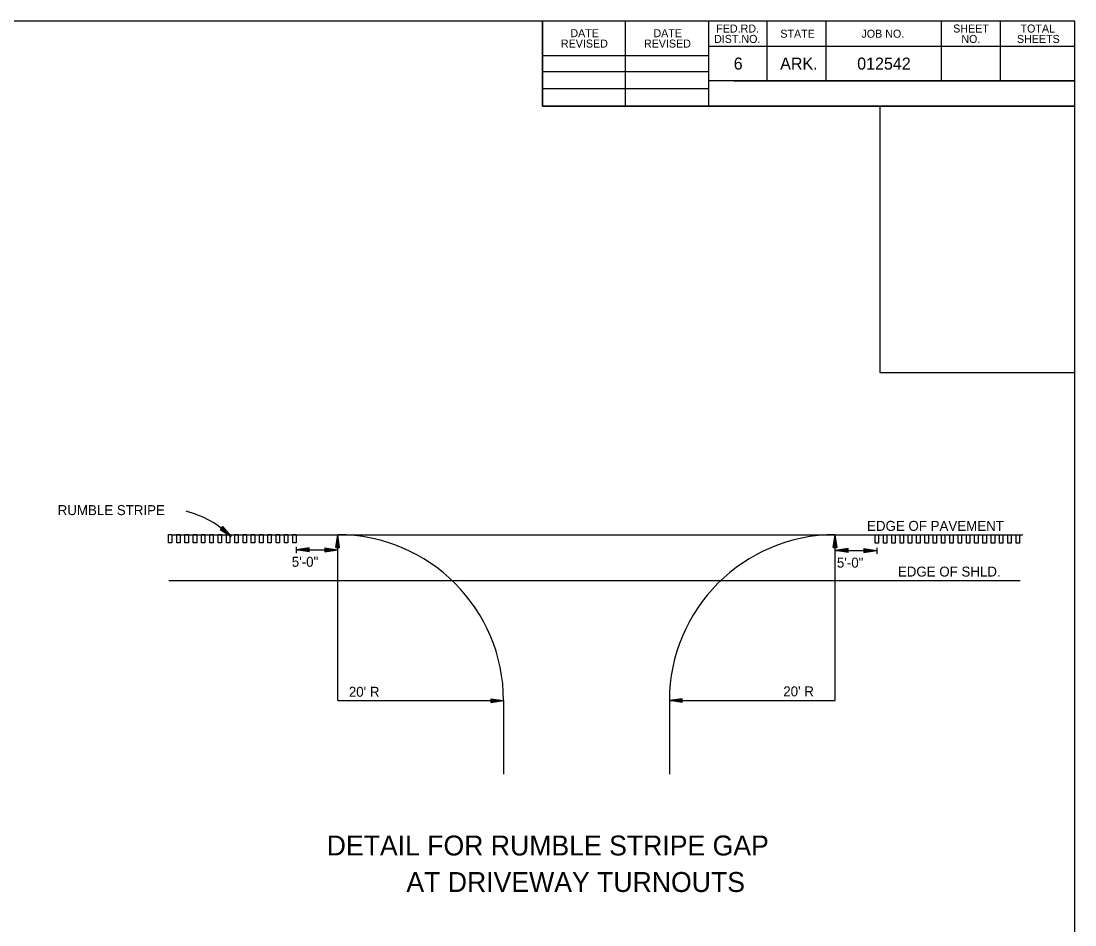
# Model space of a CAD drawing. Extents: x 1371343 to 1376243, y 378740 to 382184.
# Drawn here: x 1372386 to 1373018, y 380374 to 380915 of the extents above; entities that cross this region are included whole.
import ezdxf

# ---------------------------------------------------------------- set-up
doc = ezdxf.new("R2010")
doc.units = 0
for name, color, linetype in [('Default', 7, 'Continuous'), ('SHET_Annotations', 7, 'Continuous'), ('SHET_Border-Lines', 7, 'Continuous'), ('SHET_Border-Text', 7, 'Continuous'), ('SHET_Stamp-Prelim', 7, 'Continuous'), ('SHET_Stamp-Seal', 7, 'Continuous')]:
    doc.layers.add(name, color=color, linetype=linetype)

msp = doc.modelspace()

# ---------------------------------------------------------------- linework, layer by layer
at = {"layer": 'Default'}
for p, q in [((1372506.53, 380612.35), (1372505.05, 380610.58)), ((1372505.55, 380611.18), (1372507.71, 380609.85)), ((1372505.67, 380611.33), (1372506.72, 380610.68)), ((1372505.91, 380611.6), (1372506.72, 380610.68)), ((1372506.03, 380611.75), (1372507.71, 380609.85)), ((1372506.16, 380611.91), (1372508.71, 380609.01)), ((1372506.28, 380612.05), (1372509.69, 380608.19)), ((1372506.41, 380612.2), (1372510.71, 380607.34)), ((1372506.53, 380612.35), (1372511.69, 380606.51)), ((1372475.93, 380607.52), (1372986.72, 380607.52)), ((1372505.05, 380610.58), (1372511.69, 380606.51)), ((1372505.17, 380610.73), (1372510.71, 380607.34)), ((1372505.3, 380610.88), (1372509.69, 380608.19)), ((1372505.42, 380611.03), (1372508.71, 380609.01)), ((1372574.44, 380599.82), (1372575.6, 380607.52)), ((1372574.44, 380599.82), (1372575.6, 380607.52)), ((1372574.64, 380599.82), (1372575.6, 380606.24)), ((1372574.64, 380599.82), (1372575.6, 380606.24)), ((1372574.83, 380599.82), (1372575.6, 380604.91)), ((1372574.83, 380599.82), (1372575.6, 380604.91)), ((1372575.6, 380508.02), (1372575.6, 380607.52)), ((1372576.76, 380599.82), (1372575.6, 380607.52)), ((1372576.76, 380599.82), (1372575.6, 380607.52)), ((1372576.56, 380599.82), (1372575.6, 380606.24)), ((1372576.56, 380599.82), (1372575.6, 380606.24)), ((1372576.37, 380599.82), (1372575.6, 380604.91)), ((1372576.37, 380599.82), (1372575.6, 380604.91)), ((1372872.97, 380599.82), (1372874.12, 380607.52)), ((1372872.97, 380599.82), (1372874.12, 380607.52)), ((1372873.16, 380599.82), (1372874.12, 380606.24)), ((1372873.16, 380599.82), (1372874.12, 380606.24)), ((1372873.35, 380599.82), (1372874.12, 380604.91)), ((1372873.35, 380599.82), (1372874.12, 380604.91)), ((1372874.12, 380508.02), (1372874.12, 380607.52)), ((1372875.28, 380599.82), (1372874.12, 380607.52)), ((1372875.28, 380599.82), (1372874.12, 380607.52)), ((1372875.08, 380599.82), (1372874.12, 380606.24)), ((1372875.08, 380599.82), (1372874.12, 380606.24)), ((1372874.89, 380599.82), (1372874.12, 380604.91)), ((1372874.89, 380599.82), (1372874.12, 380604.91)), ((1372550.73, 380600.19), (1372550.73, 380596.51)), ((1372558.43, 380599.64), (1372550.73, 380598.48)), ((1372550.73, 380598.48), (1372575.6, 380598.48)), ((1372558.43, 380597.33), (1372550.73, 380598.48)), ((1372558.43, 380599.45), (1372552.01, 380598.48)), ((1372558.43, 380597.52), (1372552.01, 380598.48)), ((1372558.43, 380599.25), (1372553.34, 380598.48)), ((1372558.43, 380597.72), (1372553.34, 380598.48)), ((1372558.43, 380599.06), (1372554.62, 380598.48)), ((1372558.43, 380597.91), (1372554.62, 380598.48)), ((1372558.43, 380598.86), (1372555.93, 380598.48)), ((1372558.43, 380598.11), (1372555.93, 380598.48)), ((1372558.43, 380598.66), (1372557.21, 380598.48)), ((1372558.43, 380598.3), (1372557.21, 380598.48)), ((1372558.43, 380597.33), (1372558.43, 380599.64)), ((1372567.89, 380599.64), (1372575.6, 380598.48)), ((1372567.89, 380599.64), (1372567.89, 380597.33)), ((1372567.89, 380599.45), (1372574.31, 380598.48)), ((1372567.89, 380599.25), (1372572.99, 380598.48)), ((1372567.89, 380599.06), (1372571.7, 380598.48)), ((1372567.89, 380598.86), (1372570.4, 380598.48)), ((1372567.89, 380598.66), (1372569.11, 380598.48)), ((1372567.89, 380597.33), (1372575.6, 380598.48)), ((1372567.89, 380598.11), (1372570.4, 380598.48)), ((1372567.89, 380597.72), (1372572.99, 380598.48)), ((1372567.89, 380597.52), (1372574.31, 380598.48)), ((1372567.89, 380597.91), (1372571.7, 380598.48)), ((1372567.89, 380598.3), (1372569.11, 380598.48)), ((1372574.44, 380599.82), (1372576.76, 380599.82)), ((1372574.44, 380599.82), (1372576.76, 380599.82)), ((1372575.03, 380599.82), (1372575.6, 380603.63)), ((1372575.03, 380599.82), (1372575.6, 380603.63)), ((1372575.23, 380599.82), (1372575.6, 380602.32)), ((1372575.23, 380599.82), (1372575.6, 380602.32)), ((1372575.42, 380599.82), (1372575.6, 380601.04)), ((1372575.42, 380599.82), (1372575.6, 380601.04)), ((1372576.17, 380599.82), (1372575.6, 380603.63)), ((1372576.17, 380599.82), (1372575.6, 380603.63)), ((1372575.98, 380599.82), (1372575.6, 380602.32)), ((1372575.98, 380599.82), (1372575.6, 380602.32)), ((1372575.78, 380599.82), (1372575.6, 380601.04)), ((1372575.78, 380599.82), (1372575.6, 380601.04)), ((1372872.97, 380599.82), (1372875.28, 380599.82)), ((1372872.97, 380599.82), (1372875.28, 380599.82)), ((1372873.55, 380599.82), (1372874.12, 380603.63)), ((1372873.55, 380599.82), (1372874.12, 380603.63)), ((1372873.75, 380599.82), (1372874.12, 380602.32)), ((1372873.75, 380599.82), (1372874.12, 380602.32)), ((1372873.94, 380599.82), (1372874.12, 380601.04)), ((1372873.94, 380599.82), (1372874.12, 380601.04)), ((1372874.69, 380599.82), (1372874.12, 380603.63)), ((1372874.69, 380599.82), (1372874.12, 380603.63)), ((1372874.5, 380599.82), (1372874.12, 380602.32)), ((1372874.5, 380599.82), (1372874.12, 380602.32)), ((1372874.3, 380599.82), (1372874.12, 380601.04)), ((1372874.3, 380599.82), (1372874.12, 380601.04)), ((1372881.83, 380599.19), (1372874.12, 380598.03)), ((1372881.83, 380598.99), (1372875.41, 380598.03)), ((1372881.83, 380598.8), (1372876.73, 380598.03)), ((1372881.83, 380598.6), (1372878.02, 380598.03)), ((1372881.83, 380598.41), (1372879.32, 380598.03)), ((1372881.83, 380596.87), (1372881.83, 380599.19)), ((1372891.29, 380599.19), (1372898.99, 380598.03)), ((1372891.29, 380599.19), (1372891.29, 380596.87)), ((1372891.29, 380598.99), (1372897.71, 380598.03)), ((1372891.29, 380598.8), (1372896.38, 380598.03)), ((1372891.29, 380598.6), (1372895.1, 380598.03)), ((1372891.29, 380598.4), (1372893.79, 380598.03)), ((1372898.99, 380599.74), (1372898.99, 380596.06)), ((1372874.12, 380598.03), (1372898.99, 380598.03)), ((1372881.83, 380596.87), (1372874.12, 380598.03)), ((1372881.83, 380597.07), (1372875.41, 380598.03)), ((1372881.83, 380597.26), (1372876.73, 380598.03)), ((1372881.83, 380597.46), (1372878.02, 380598.03)), ((1372881.83, 380597.66), (1372879.32, 380598.03)), ((1372881.83, 380598.21), (1372880.61, 380598.03)), ((1372881.83, 380597.85), (1372880.61, 380598.03)), ((1372891.29, 380598.21), (1372892.51, 380598.03)), ((1372891.29, 380596.87), (1372898.99, 380598.03)), ((1372891.29, 380597.65), (1372893.79, 380598.03)), ((1372891.29, 380597.26), (1372896.38, 380598.03)), ((1372891.29, 380597.07), (1372897.71, 380598.03)), ((1372891.29, 380597.46), (1372895.1, 380598.03)), ((1372891.29, 380597.85), (1372892.51, 380598.03)), ((1372474.28, 380580.11), (1372985.07, 380580.11)), ((1372575.6, 380508.02), (1372675.11, 380508.02)), ((1372667.4, 380509.17), (1372675.11, 380508.02)), ((1372667.4, 380509.17), (1372667.4, 380506.86)), ((1372667.4, 380509.17), (1372675.11, 380508.02)), ((1372667.4, 380509.17), (1372667.4, 380506.86)), ((1372667.4, 380508.98), (1372673.82, 380508.02)), ((1372667.4, 380508.98), (1372673.82, 380508.02)), ((1372667.4, 380508.78), (1372672.49, 380508.02)), ((1372667.4, 380508.78), (1372672.49, 380508.02)), ((1372667.4, 380508.59), (1372671.21, 380508.02)), ((1372667.4, 380508.59), (1372671.21, 380508.02)), ((1372667.4, 380508.39), (1372669.91, 380508.02)), ((1372667.4, 380508.39), (1372669.91, 380508.02)), ((1372667.4, 380508.2), (1372668.62, 380508.02)), ((1372667.4, 380508.2), (1372668.62, 380508.02)), ((1372667.4, 380506.86), (1372675.11, 380508.02)), ((1372667.4, 380507.64), (1372669.91, 380508.02)), ((1372667.4, 380507.25), (1372672.49, 380508.02)), ((1372667.4, 380507.05), (1372673.82, 380508.02)), ((1372667.4, 380507.44), (1372671.21, 380508.02)), ((1372667.4, 380507.84), (1372668.62, 380508.02)), ((1372667.4, 380506.86), (1372675.11, 380508.02)), ((1372667.4, 380507.64), (1372669.91, 380508.02)), ((1372667.4, 380507.25), (1372672.49, 380508.02)), ((1372667.4, 380507.05), (1372673.82, 380508.02)), ((1372667.4, 380507.44), (1372671.21, 380508.02)), ((1372667.4, 380507.84), (1372668.62, 380508.02)), ((1372675.11, 380508.02), (1372675.11, 380463.96)), ((1372782.32, 380509.17), (1372774.61, 380508.02)), ((1372782.32, 380509.17), (1372774.61, 380508.02)), ((1372774.61, 380508.02), (1372774.61, 380463.96)), ((1372774.61, 380508.02), (1372874.12, 380508.02)), ((1372782.32, 380506.86), (1372774.61, 380508.02)), ((1372782.32, 380506.86), (1372774.61, 380508.02)), ((1372782.32, 380508.98), (1372775.9, 380508.02)), ((1372782.32, 380508.98), (1372775.9, 380508.02)), ((1372782.32, 380507.05), (1372775.9, 380508.02)), ((1372782.32, 380507.05), (1372775.9, 380508.02)), ((1372782.32, 380508.78), (1372777.23, 380508.02)), ((1372782.32, 380508.78), (1372777.23, 380508.02)), ((1372782.32, 380507.25), (1372777.23, 380508.02)), ((1372782.32, 380507.25), (1372777.23, 380508.02)), ((1372782.32, 380508.59), (1372778.51, 380508.02)), ((1372782.32, 380508.59), (1372778.51, 380508.02)), ((1372782.32, 380507.44), (1372778.51, 380508.02)), ((1372782.32, 380507.44), (1372778.51, 380508.02)), ((1372782.32, 380508.39), (1372779.81, 380508.02)), ((1372782.32, 380508.39), (1372779.81, 380508.02)), ((1372782.32, 380507.64), (1372779.81, 380508.02)), ((1372782.32, 380507.64), (1372779.81, 380508.02)), ((1372782.32, 380508.2), (1372781.1, 380508.02)), ((1372782.32, 380508.2), (1372781.1, 380508.02)), ((1372782.32, 380507.84), (1372781.1, 380508.02)), ((1372782.32, 380507.84), (1372781.1, 380508.02)), ((1372782.32, 380506.86), (1372782.32, 380509.17)), ((1372782.32, 380506.86), (1372782.32, 380509.17))]:
    msp.add_line(p, q, dxfattribs=at)
for points in [[(1372474.03, 380602.59), (1372474.03, 380607.57), (1372476.11, 380607.57), (1372476.11, 380602.59), (1372474.03, 380602.59)], [(1372479.01, 380602.59), (1372479.01, 380607.57), (1372481.08, 380607.57), (1372481.08, 380602.59), (1372479.01, 380602.59)], [(1372483.98, 380602.59), (1372483.98, 380607.57), (1372486.06, 380607.57), (1372486.06, 380602.59), (1372483.98, 380602.59)], [(1372488.96, 380602.59), (1372488.96, 380607.57), (1372491.03, 380607.57), (1372491.03, 380602.59), (1372488.96, 380602.59)], [(1372493.93, 380602.59), (1372493.93, 380607.57), (1372496, 380607.57), (1372496, 380602.59), (1372493.93, 380602.59)], [(1372498.91, 380602.59), (1372498.91, 380607.57), (1372500.98, 380607.57), (1372500.98, 380602.59), (1372498.91, 380602.59)], [(1372503.88, 380602.59), (1372503.88, 380607.57), (1372505.95, 380607.57), (1372505.95, 380602.59), (1372503.88, 380602.59)], [(1372508.86, 380602.59), (1372508.86, 380607.57), (1372510.93, 380607.57), (1372510.93, 380602.59), (1372508.86, 380602.59)], [(1372513.83, 380602.59), (1372513.83, 380607.57), (1372515.9, 380607.57), (1372515.9, 380602.59), (1372513.83, 380602.59)], [(1372518.81, 380602.59), (1372518.81, 380607.57), (1372520.88, 380607.57), (1372520.88, 380602.59), (1372518.81, 380602.59)], [(1372523.78, 380602.59), (1372523.78, 380607.57), (1372525.85, 380607.57), (1372525.85, 380602.59), (1372523.78, 380602.59)], [(1372528.75, 380602.59), (1372528.75, 380607.57), (1372530.83, 380607.57), (1372530.83, 380602.59), (1372528.75, 380602.59)], [(1372533.73, 380602.59), (1372533.73, 380607.57), (1372535.8, 380607.57), (1372535.8, 380602.59), (1372533.73, 380602.59)], [(1372538.7, 380602.59), (1372538.7, 380607.57), (1372540.78, 380607.57), (1372540.78, 380602.59), (1372538.7, 380602.59)], [(1372543.68, 380602.59), (1372543.68, 380607.57), (1372545.75, 380607.57), (1372545.75, 380602.59), (1372543.68, 380602.59)], [(1372548.65, 380602.59), (1372548.65, 380607.57), (1372550.73, 380607.57), (1372550.73, 380602.59), (1372548.65, 380602.59)], [(1372898.06, 380602.54), (1372898.06, 380607.51), (1372900.13, 380607.51), (1372900.13, 380602.54), (1372898.06, 380602.54)], [(1372903.03, 380602.54), (1372903.03, 380607.51), (1372905.1, 380607.51), (1372905.1, 380602.54), (1372903.03, 380602.54)], [(1372908.01, 380602.54), (1372908.01, 380607.51), (1372910.08, 380607.51), (1372910.08, 380602.54), (1372908.01, 380602.54)], [(1372912.98, 380602.54), (1372912.98, 380607.51), (1372915.05, 380607.51), (1372915.05, 380602.54), (1372912.98, 380602.54)], [(1372917.95, 380602.54), (1372917.95, 380607.51), (1372920.03, 380607.51), (1372920.03, 380602.54), (1372917.95, 380602.54)], [(1372922.93, 380602.54), (1372922.93, 380607.51), (1372925, 380607.51), (1372925, 380602.54), (1372922.93, 380602.54)], [(1372927.9, 380602.54), (1372927.9, 380607.51), (1372929.98, 380607.51), (1372929.98, 380602.54), (1372927.9, 380602.54)], [(1372932.88, 380602.54), (1372932.88, 380607.51), (1372934.95, 380607.51), (1372934.95, 380602.54), (1372932.88, 380602.54)], [(1372937.85, 380602.54), (1372937.85, 380607.51), (1372939.93, 380607.51), (1372939.93, 380602.54), (1372937.85, 380602.54)], [(1372942.83, 380602.54), (1372942.83, 380607.51), (1372944.9, 380607.51), (1372944.9, 380602.54), (1372942.83, 380602.54)], [(1372947.8, 380602.54), (1372947.8, 380607.51), (1372949.88, 380607.51), (1372949.88, 380602.54), (1372947.8, 380602.54)], [(1372952.78, 380602.54), (1372952.78, 380607.51), (1372954.85, 380607.51), (1372954.85, 380602.54), (1372952.78, 380602.54)], [(1372957.75, 380602.54), (1372957.75, 380607.51), (1372959.82, 380607.51), (1372959.82, 380602.54), (1372957.75, 380602.54)], [(1372962.73, 380602.54), (1372962.73, 380607.51), (1372964.8, 380607.51), (1372964.8, 380602.54), (1372962.73, 380602.54)], [(1372967.7, 380602.54), (1372967.7, 380607.51), (1372969.77, 380607.51), (1372969.77, 380602.54), (1372967.7, 380602.54)], [(1372972.68, 380602.54), (1372972.68, 380607.51), (1372974.75, 380607.51), (1372974.75, 380602.54), (1372972.68, 380602.54)], [(1372977.65, 380602.54), (1372977.65, 380607.51), (1372979.72, 380607.51), (1372979.72, 380602.54), (1372977.65, 380602.54)], [(1372982.63, 380602.54), (1372982.63, 380607.51), (1372984.7, 380607.51), (1372984.7, 380602.54), (1372982.63, 380602.54)]]:
    msp.add_lwpolyline(points, dxfattribs=at)
for centre, radius, start, end in [((1372468.86, 380561.43), 62.18, 46.46131, 75.27856), ((1372575.6, 380508.02), 99.51, 0, 90), ((1372874.12, 380508.02), 99.51, 90, 180)]:
    msp.add_arc(centre, radius, start, end, dxfattribs=at)
at = {"layer": 'SHET_Border-Lines'}
for p, q in [((1372698.46, 380864.55), (1372698.46, 380915.49)), ((1372748.28, 380864.55), (1372748.28, 380915.49)), ((1372798.11, 380915.49), (1372798.11, 380864.55)), ((1372832.99, 380915.49), (1372832.99, 380879.71)), ((1372868.39, 380915.49), (1372868.39, 380879.71)), ((1372937.64, 380915.49), (1372937.64, 380879.71)), ((1372973.04, 380915.49), (1372973.04, 380879.71)), ((1373017.92, 380900.34), (1372798.11, 380900.34)), ((1373017.92, 380900.44), (1373017.92, 380900.44)), ((1372698.46, 380894.77), (1372798.11, 380894.77)), ((1372698.46, 380885.18), (1372798.11, 380885.18)), ((1373017.92, 380879.71), (1372798.11, 380879.71)), ((1372813.21, 380879.71), (1373017.92, 380879.71)), ((1372698.46, 380875.17), (1372798.11, 380875.17)), ((1373017.92, 380864.55), (1372698.46, 380864.55))]:
    msp.add_line(p, q, dxfattribs=at)
for points in [[(1371367.92, 379865.49), (1373017.92, 379865.49), (1373017.92, 380915.49), (1371367.92, 380915.49)], [(1372698.46, 380864.55), (1373017.92, 380864.55), (1373017.92, 380915.49), (1372698.46, 380915.49)]]:
    msp.add_lwpolyline(points, close=True, dxfattribs=at)
at = {"layer": 'SHET_Stamp-Prelim'}
msp.add_lwpolyline([(1372907.92, 380864.51), (1372908.1, 380864.51), (1372908.1, 380864.55), (1372907.92, 380864.55)], close=True, dxfattribs=at)
at = {"layer": 'SHET_Stamp-Seal'}
msp.add_lwpolyline([(1372900.91, 380704.83), (1373017.92, 380704.83), (1373017.92, 380864.55), (1372900.91, 380864.55)], close=True, dxfattribs=at)

# ---------------------------------------------------------------- texts
at = {"layer": 'Default'}
for s, height, p in [('RUMBLE STRIPE', 5.9696, (1372407.62, 380619.27)), ('EDGE OF PAVEMENT', 5.9696, (1372893.21, 380609.82)), ('5\'-0"', 5.97, (1372548.06, 380588.28)), ('5\'-0"', 5.97, (1372875.13, 380587.77)), ('EDGE OF SHLD.', 5.9696, (1372911.7, 380582.41)), ("20' R", 5.97, (1372582.3, 380510.34)), ("20' R", 5.97, (1372842.94, 380510.58)), ('DETAIL FOR RUMBLE STRIPE GAP', 11.9393, (1372569.02, 380415.18)), ('AT DRIVEWAY TURNOUTS', 11.9393, (1372616.83, 380393.29))]:
    msp.add_text(s, height=height, dxfattribs=at).set_placement(p)
at = {"layer": 'SHET_Annotations'}
for s, p in [('6', (1372813.21, 380886.42)), ('ARK.', (1372841.08, 380886.42)), ('012542', (1372887.29, 380886.42))]:
    msp.add_text(s, height=7.2, dxfattribs=at).set_placement(p)
at = {"layer": 'SHET_Border-Text'}
for s, p in [('DATE', (1372715.21, 380905.85)), ('DATE', (1372765.04, 380905.85)), ('FED.RD.', (1372802.72, 380908.64)), ('STATE', (1372841.17, 380905.52)), ('JOB NO.', (1372889.84, 380905.52)), ('SHEET', (1372944.87, 380908.64)), ('TOTAL', (1372985.28, 380908.64)), ('REVISED', (1372709.53, 380899.61)), ('REVISED', (1372759.36, 380899.61)), ('DIST.NO.', (1372801.41, 380902.4)), ('NO.', (1372949.76, 380902.4)), ('SHEETS', (1372983.13, 380902.4))]:
    msp.add_text(s, height=4.8, dxfattribs=at).set_placement(p)
at = {"layer": 'SHET_Stamp-Prelim'}
for s, height, p in [('PRELIMINARY', 0.013, (1372907.94, 380864.53)), ('SUBJECT TO REVISION', 0.009, (1372907.95, 380864.52))]:
    msp.add_text(s, height=height, dxfattribs=at).set_placement(p)

doc.saveas('drawing.dxf')
